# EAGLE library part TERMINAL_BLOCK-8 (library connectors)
8 Pin Terminal block with .25" centers purchased from All Electronics - Part #Ter-98 Contacts Rated at 5A and 150V RDI Carol Stream - 3 Series
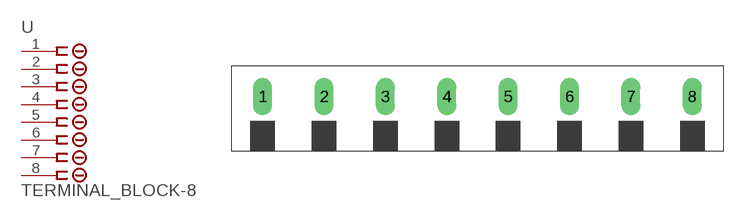
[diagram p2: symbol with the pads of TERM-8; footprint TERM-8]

Designator prefix -

## TERMINAL_BLOCK-8  [TERM-8]
1  1
2  2
3  3
4  4
5  5
6  6
7  7
8  8

## Footprint TERM-8 (pad centres in mm)
8 position Terminal Strip Pin's .235" grid
drill 1.3 long: 1 0,0; 2 6.35,0; 3 12.7,0; 4 19.05,0; 5 25.4,0; 6 31.75,0; 7 38.1,0; 8 44.45,0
